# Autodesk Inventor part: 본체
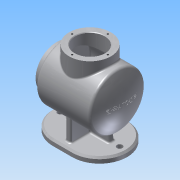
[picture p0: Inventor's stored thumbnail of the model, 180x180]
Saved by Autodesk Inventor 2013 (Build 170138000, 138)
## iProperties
Created: 2016-04
Part Number: 본체
Material: 알루미늄 6061
Document SubType Name: Modeling
Designer: Administrator
Density: 2.71 g/cm^3
Mass: 934.578 g
Surface Area: 1234.74 cm^2
Volume: 344.863 cm^3
Author: Administrator
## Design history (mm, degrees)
sketch "스케치1"
  geometry: L1 (-17.5, 50)-(17.5, 50); L2 (17.5, -50)-(-17.5, -50); A1 r 50 centre (17.5, 0) between (17.5, -50) and (17.5, 50); A2 r 50 centre (-17.5, 0) between (-17.5, 50) and (-17.5, -50); 2 further points
  constraints: 4 end point, 4 point on circle, 4 tangent, 2 centre point, 1 horizontal, 1 horizontal alignment, 1 midpoint, 1 parallel, 1 vertical alignment
  dimensions: "d0" = 135 dimension on A1 A2; "d2" = 100 distance between parallel lines of L2 L1
extrude "돌출1" new body sketch "스케치1" distance "d3" = 10; taper "d4" = 0 deg
sketch "스케치3"
  geometry: L1 (-46, 126)-(47.104, 126); L2 (-49, 129)-(49, 129); L3 (-61, 79)-(61, 79); L4 (-46, 106)-(-46, 126); L5 (-49, 117)-(-49, 129); L6 (-61, 106)-(-46, 106); L7 (-61, 106)-(-61, 117); L8 (-61, 117)-(-49, 117); L9 (17.5, 0)-(-17.5, 0) reference; A1 r 117 centre (-58.977, 76.646) between (57.999, 79) and (47.104, 126); A2 r 120 centre (-58.977, 76.646) between (61, 79) and (49, 129); 3 further points
  constraints: 17 end point, 4 point on circle, 3 parallel, 2 centre point, 2 horizontal, 2 midpoint, 2 perpendicular, 2 vertical alignment, 1 point on line, 1 vertical
  dimensions: "d17" = 122 distance of L3.end L3.start; "d18" = 54 diameter of L6 L3; "d19" = 76 diameter of L8 L3; "d20" = 94 diameter of L1 L3; "d21" = 100 diameter of L2 L3; "d22" = 12 distance of L7.end L5.start; "d23" = 120 radius of A2; "d24" = 12 horizontal distance of L3.end L2.end; "d25" = 3 distance between parallel lines of L4 L5; "d26" = 3 radial gap between concentric circles of A2 A1; "d27" = 79 distance from line of L9 point (0, 79)
revolve "회전1" sketch "스케치3" stored, may be unused: angle "d28" = 90 deg
sketch "스케치5"
  geometry: L1 (-17.5, 10)-(-67.5, 10) reference; L2 (67.5, 10)-(17.5, 10) reference; L3 (-49, 29)-(49, 29) reference; L4 (-40, 10)-(-36.25, 31.267); L5 (-36.25, 31.267)-(36.25, 31.267); L6 (36.25, 31.267)-(40, 10); 2 further points
  constraints: 6 end point, 2 point on line, 1 equal length, 1 midpoint, 1 parallel, 1 vertical alignment
  dimensions: "d37" = 40 horizontal distance of point (0, 0) L4.start; "d38" = 100 deg angle of L4 L1; "d39" = 72.5 distance of L4.end L5.end
feature "리브1" sketch "스케치5" dims "d40" = 1, "d41" = 10, "d42" = 0, "d43" = 0, "d44" = 1, "d45" = 1
node "작업 평면1"
sketch "스케치8"
  geometry: L1 (-40, 51.43)-(-40, 10); L2 (40, 51.43)-(40, 10); L3 (50, 10)-(-50, 10) reference; A1 r 49 centre (0, 79.732) between (-40, 51.43) and (40, 51.43); 1 further point
  constraints: 4 end point, 2 horizontal alignment, 2 point on circle, 2 point on line, 1 centre point, 1 parallel, 1 vertical
  dimensions: "d61" = 80 distance between parallel lines of L2 L1; "d68" = 49 radius of A1; "d69" = 40 horizontal distance of L1.end point (0, 0); "d70" = 79.73167 distance of A1.centre point (0, 0)
feature "리브2" sketch "스케치8" dims "d62" = 1, "d63" = 10, "d64" = 0, "d65" = 0, "d66" = 1, "d67" = 1
sketch "스케치9"
  geometry: 3 further points
  constraints: 2 horizontal alignment
  dimensions: "d71" = 54 distance of point (0, 0) point (-54, 0); "d72" = 54 distance of point (54, 0) point (0, 0)
hole "구멍1" sketch "스케치9" at (-54, 0), (54, 0) diameter "d73" = 10; stored, may be unused: countersink angle "d77" = 90 deg, drill point angle "d79" = 118 deg; dims "d74" = 6, "d75" = 4, "d76" = 2, "d78" = 8
node "작업 평면2"
sketch "스케치10"
  geometry: C1 r 38 at (0, 0); 1 further point
  constraints: 1 centre point, 1 coincident
  dimensions: "d81" = 76 diameter of C1
extrude "돌출4" join sketch "스케치10" distance "d83" = 38; taper "d84" = 0 deg
sketch "스케치11"
  geometry: C1 r 47 at (0, 79) reference; 1 further point
feature "돌출 곡면2" sketch "스케치11" dims "d85" = 78, "d86" = 0
feature "분할1"
hole "구멍2" diameter "d89" = 54; stored, may be unused: countersink angle "d93" = 90 deg, drill point angle "d95" = 118 deg; dims "d87" = 10, "d88" = 10, "d90" = 6, "d91" = 4, "d92" = 2, "d94" = 40
sketch "스케치12"
  geometry: A1 r 32.5 centre (0, 0) between (-32.5, 0) and (0, -32.5); 3 further points
  constraints: 4 point on circle, 3 horizontal alignment, 2 vertical alignment, 1 centre point
  dimensions: "d96" = 79 distance of point (79, 0) A1.centre; "d97" = 65 diameter of A1
hole "구멍3" sketch "스케치12" at (-32.5, 0), (0, -32.5), (0, 32.5), (32.5, 0) diameter "d98" = 3.242; stored, may be unused: countersink angle "d102" = 90 deg, drill point angle "d104" = 118 deg; dims "d99" = 8, "d100" = 4, "d101" = 2, "d103" = 10
sketch "스케치13"
  geometry: A1 r 32.5 centre (0, 0) between (0, 32.5) and (-32.5, 0); 3 further points
  constraints: 4 point on circle, 2 horizontal alignment, 2 vertical alignment, 1 centre point, 1 coincident
  dimensions: "d105" = 65 diameter of A1
hole "구멍4" sketch "스케치13" at (0, 32.5), (-32.5, 0), (0, -32.5), (32.5, 0) diameter "d107" = 3.242; stored, may be unused: countersink angle "d111" = 90 deg, drill point angle "d113" = 118 deg; dims "d108" = 8, "d109" = 4, "d110" = 2, "d112" = 10
node "작업 평면3"
node "작업 평면4"
sketch "스케치14"
  geometry: 2 further points
  constraints: 1 vertical alignment, 1 other
  dimensions: "d116" = 79 distance of point (0, 0) point (0, 79)
feature "엠보싱1" sketch "스케치14" dims "d0" = 135, "d2" = 100, "d117" = 0.5, "d118" = 0
chamfer "모따기1" distance "d119" = 3; stored, may be unused: second distance "d120" = 2, angle "d121" = 45 deg
chamfer "모따기2" distance "d122" = 1; stored, may be unused: second distance "d123" = 2, angle "d124" = 45 deg
fillet "모깎기1" dims "d125" = 5
fillet "모깎기2" dims "d126" = 2
fillet "모깎기3" dims "d127" = 3
fillet "모깎기4" dims "d128" = 3
node "솔리드1"
node "곡면2"
other parameters: "d46" = 144, "d80" = 144, "d114" = -48, "d115" = -61
